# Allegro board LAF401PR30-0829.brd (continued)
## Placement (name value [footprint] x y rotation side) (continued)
CZ84  68P_0402_50V8J  [C_0402]  214.81 11.96 0 top
CZ85  100P_0402_50V8J  [C_0402]  214.84 14.93 0 top
CZ86  100P_0402_50V8J  [C_0402]  214.84 15.84 0 top
CZ87  100P_0402_50V8J  [C_0402]  214.84 16.76 0 top
CZ88  68P_0402_50V8J  [C_0402]  217.11 20.12 0 top
CZ89  68P_0402_50V8J  [C_0402]  217.11 21.14 0 top
CZ90  0.1U_0201_10V6K  [C_0201]  214.91 18.45 270 top
CZ91  100P_0402_50V8J  [C_0402]  215.27 13.99 0 top
CZ92  100P_0402_50V8J  [C_0402]  215.27 13.1 0 top
CZ93  0.1U_0201_10V6K  [C_0201]  279.91 45.97 270 top
CZ101  0.1U_0201_10V6K  [C_0201]  124.34 84.22 180 bottom
CZ103  0.1U_0201_10V6K  [C_0201]  123.44 29.37 90 top
CZ104  0.1U_0402_10V7K  [C_0402]  128.96 26.37 0 top
CZ106  0.1U_0201_10V6K  [C_0201]  144.56 86.63 0 bottom
CZ109  470P_0402_50V7K  [C_0402]  278.72 49.92 0 bottom
CZ110  470P_0402_50V7K  [C_0402]  278.72 50.81 0 bottom
CZ111  0.1U_0201_10V6K  [C_0201]  276.61 52.22 180 bottom
CZ112  0.1U_0201_10V6K  [C_0201]  204.43 9.68 180 top
CZ113  470P_0402_50V7K  [C_0402]  207.4 6.76 45 top
CZ114  1000P_0402_50V7K  [C_0402]  205.06 6.06 90 top
CZ115  0.1U_0201_10V6K  [C_0201]  206.56 3.05 270 top
CZ116  0.1U_0201_10V6K  [C_0201]  194.91 17.8 0 top
CZ117  470P_0402_50V7K  [C_0402]  194.94 17.04 0 top
CZ118  470P_0402_50V7K  [C_0402]  194.94 16.02 0 top
CZ119  0.1U_0201_10V6K  [C_0201]  277.41 46.63 180 bottom
CZ120  0.1U_0201_10V6K  [C_0201]  272.55 49.42 90 top
CZ121  470P_0402_50V7K  [C_0402]  270.52 48.23 270 top
CZ122  0.1U_0201_10V6K  [C_0201]  192.96 14.5 180 top
CZ124  2200P_0402_50V7K  [C_0402]  277.32 47.39 180 bottom
CZ125  0.1U_0201_10V6K  [C_0201]  277.25 73.39 90 top
CZ126  220P_0402_50V7K  [C_0402]  275.72 71.09 270 top
CZ127  1000P_0402_50V7K  [C_0402]  274.71 71.09 270 top
CZ128  0.1U_0201_10V6K  [C_0201]  272.93 73.55 90 top
CZ129  0.1U_0201_10V6K  [C_0201]  279.95 39.96 180 bottom
CZ130  470P_0402_50V7K  [C_0402]  281.31 41.5 270 bottom
CZ133  0.1U_0201_10V6K  [C_0201]  289.18 62.63 90 bottom
CZ134  0.01UF_0402_25V7K  [C_0402]  283.8 66.95 180 top
CZ135  0.22U_0402_10V6K  [C_0402]  282.88 65.99 0 top
CZ136  0.22U_0402_10V6K  [C_0402]  282.88 65.04 0 top
CZ141  0.22U_0402_10V6K  [C_0402]  282.88 63.14 0 top
CZ142  0.22U_0402_10V6K  [C_0402]  282.88 64.09 0 top
CZ197  470P_0402_50V7K  [C_0402]  270.69 53.36 0 top
CZ198  100P_0402_50V8J  [C_0402]  291.34 50.51 270 top
CZ200  0.1U_0402_25V6K  [C_0402]  114.66 86.02 180 bottom
CZ210  100P_0402_50V8J  [C_0402]  206.02 7.77 0 top
CZ211  100P_0402_50V8J  [C_0402]  205.72 3.27 270 top
CZ212  27P_0402_50V8J  [C_0402]  283.52 46.75 270 bottom
CZ1000  1U_0201_6.3V6M  [C_0201]  137.79 86.68 180 bottom
CZ1001  1U_0201_6.3V6M  [C_0201]  137.79 86.1 180 bottom
CZ1002  1U_0201_6.3V6M  [C_0201]  126.81 26.64 0 top
CZ1003  1U_0201_6.3V6M  [C_0201]  126.81 25.98 0 top
CZ1004  1U_0201_6.3V6M  [C_0201]  133.33 82.82 90 bottom
CZ1005  1U_0201_6.3V6M  [C_0201]  133.91 82.82 90 bottom
DA1  AZ5123-02S.R7G_SOT23-3  [L03ESDL5V0CC3-2_SOT23-3]  311.82 35.07 90 top
DA2  PESD5V0U2BT_SOT23-3  [L03ESDL5V0CC3-2_SOT23-3]  311.82 31.01 90 top
DA3  AZ5123-02S.R7G_SOT23-3  [L03ESDL5V0CC3-2_SOT23-3]  309.73 39.13 270 top
DA6  PESD5V0U2BT_SOT23-3  [L03ESDL5V0CC3-2_SOT23-3]  284.08 29.74 270 top
DA7  PESD5V0U2BT_SOT23-3  [L03ESDL5V0CC3-2_SOT23-3]  284.08 34.31 270 top
DA8  RB751S40_SOD523-2  [RB520SM-30T2R_EMD2-2]  293.81 42.02 0 top
DC1  RB751S40_SOD523-2  [RB520SM-30T2R_EMD2-2]  185.07 34.75 180 top
DC2  RB751S40_SOD523-2  [RB520SM-30T2R_EMD2-2]  183.37 36.02 0 top
DE1  BZV55-B5V6_SOD80C2  [BZV55-B5V1_SOD80C2]  266.88 40.68 180 top
DE2  RB751S40_SOD523-2  [RB520SM-30T2R_EMD2-2]  317.76 60.83 90 top
DI1  -  [L05ESDL5V0NA-4_SLP2510P8-10-9]  19.94 70.38 270 top
DI2  -  [AZC199-02SPR7G_SOT23-3]  24.14 71.27 270 top
DI3  -  [AZC199-02SPR7G_SOT23-3]  80.46 101.72 180 bottom
DI4  -  [L05ESDL5V0NA-4_SLP2510P8-10-9]  308.81 54.87 90 top
DI5  -  [AZC199-02SPR7G_SOT23-3]  309.12 50.82 180 top
DI6  -  [L05ESDL5V0NA-4_SLP2510P8-10-9]  80.41 102.2 180 top
DT1  -  [1N4148WS-7-F_SOD323-2]  38.67 98.57 180 bottom
DT2  -  [1N4148WS-7-F_SOD323-2]  38.67 96.79 180 bottom
DT3  -  [1N4148WS-7-F_SOD323-2]  35.69 94.45 270 bottom
DT4  -  [L30ESD24VC3-2_SOT23-3]  12.83 90.21 0 bottom
DT5  AZ5B75-01B_CSP0603P2Y  [ESD8011MUT5G_X3DFN2-2-S]  11.86 94.2 270 bottom
DT6  AZ5B75-01B_CSP0603P2Y  [ESD8011MUT5G_X3DFN2-2-S]  11.86 95.04 90 bottom
DT9  AZ5B75-01B_CSP0603P2Y  [ESD8011MUT5G_X3DFN2-2-S]  11.83 100.05 270 bottom
DT10  AZ5B75-01B_CSP0603P2Y  [ESD8011MUT5G_X3DFN2-2-S]  11.83 100.9 90 bottom
DT13  AZ5B75-01B_CSP0603P2Y  [ESD8011MUT5G_X3DFN2-2-S]  11.4 91.42 270 bottom
DT14  AZ5B75-01B_CSP0603P2Y  [ESD8011MUT5G_X3DFN2-2-S]  11.4 92.26 90 bottom
DT17  AZ5B75-01B_CSP0603P2Y  [ESD8011MUT5G_X3DFN2-2-S]  11.83 100.9 90 top
DT18  AZ5B75-01B_CSP0603P2Y  [ESD8011MUT5G_X3DFN2-2-S]  11.83 100.05 270 top
DT39  -  [L05ESDL5V0NA-4_SLP2510P8-10-9]  12.33 96.55 270 bottom
DT40  -  [L05ESDL5V0NA-4_SLP2510P8-10-9]  12.63 91.22 270 top
DV1  -  [BAT54CW_SOT323-3]  105.67 86.12 180 bottom
DV2  -  [BAT54CW_SOT323-3]  103.13 85.87 180 bottom
DV3  -  [BAT54CW_SOT323-3]  92.97 83.78 0 bottom
DV4  -  [AZC199-02SPR7G_SOT23-3]  116.44 87.33 90 bottom
DV5  -  [PJDLC05C_SOT23-3]  314.3 85.04 90 bottom
DV6  -  [PJDLC05C_SOT23-3]  314.3 80.98 90 bottom
DZ1  RB751S40_SOD523-2  [RB520SM-30T2R_EMD2-2]  216.57 9.38 180 top
DZ2  RB751S40_SOD523-2  [RB520SM-30T2R_EMD2-2]  216.57 10.65 180 top
DZ5  RB751S40_SOD523-2  [RB520SM-30T2R_EMD2-2]  292.83 49.17 90 top
DZ6  RB751S40_SOD523-2  [RB520SM-30T2R_EMD2-2]  293.53 45.75 90 top
DZ7  RB751S40_SOD523-2  [RB520SM-30T2R_EMD2-2]  221.31 22.52 180 top
DZ8  RB751S40_SOD523-2  [RB520SM-30T2R_EMD2-2]  154.44 38 90 top
DZ9  -  [BAT54CW_SOT323-3]  184 13.52 180 top
FD1  FIDUCIAL MARK~D  [FIDUCIAL_C40M80]  315.36 95.48 0 top
FD2  FIDUCIAL MARK~D  [FIDUCIAL_C40M80]  15.37 3.83 0 top
FD3  FIDUCIAL MARK~D  [FIDUCIAL_C40M80]  15.37 3.83 180 bottom
FD4  FIDUCIAL MARK~D  [FIDUCIAL_C40M80]  323.22 97.3 180 bottom
H1  -  [H_3P8]  87.65 73.4 0 top
H2  -  [H_3P8]  87.65 45.4 0 top
H3  -  [H_3P8]  144.25 81.75 0 top
H4  -  [H_3P8]  149.15 47.45 0 top
H5  -  [H_1P1N]  98.5 71.86 0 top
H6  -  [H_1P1N]  139.62 48.75 0 top
H7  -  [H_3P2]  234.9 15.5 0 top
H8  -  [H_3P2]  296.05 87.5 0 top
H9  H_2P3  [H_2P3-G]  141.95 118.9 0 top
H10  H_3P0  [H_3P0-G]  310.15 98.9 0 top
H12  H_2P5  [H_2P5-G]  323.65 22.4 0 top
H14  H_4P0  [H_4P0-G]  267.65 58.9 0 top
H15  H_4P0  [H_4P0-G]  269.65 101.4 0 top
H16  H_2P3  [H_2P3-G]  67.35 116.9 0 top
H17  H_4P0  [H_4P0-G]  113.15 2.1 0 top
H18  H_2P5  [H_2P5-G]  4.45 3 0 top
H20  H_4P0  [H_4P0-G]  202.75 37.1 0 top
H22  H_4P0  [H_4P0-G]  241 1.5 0 top
H23  H_2P5  [H_2P5-G]  6.25 106.1 0 top
H24  H_2P5  [H_2P5-G]  6.25 88 0 top
H25  H_2P2  [H_2P2-G]  4.45 8.4 0 top
H26  H_2P3  [H_2P3-G]  116.55 116.9 0 top
H28  H_2P5  [H_2P5-G]  268.15 106.3 0 top
H29  H_2P5  [H_2P5-G]  282.15 110.4 0 top
H32  H_2P6X3P6  [H_2P6X3P6-G]  318.05 22.4 90 top
H34  -  [H_3P3]  89.35 94.4 0 top
H35  -  [H_3P3]  123.75 94.4 0 top
H38  -  [H_3P8]  147.55 117.4 0 top
H42  -  [H_0P7N]  121.59 116.25 0 top
H43  -  [H_0P9N]  130.79 103.2 0 top
JAPS1  ACES_50506-01841-P01  [ACES_50506-01841-P01_18P]  317.63 62.25 90 bottom
JCRT1  CCM_C070546HR015M29CZR  [CCM_C070546HR015M29CZR_15P-T]  322.15 83.18 90 bottom
JDB1  JXT_FP241AH-006GAAM  [JXT_FP241AH-006GAAM_6P]  32.37 97.09 180 top
JDEG1  JXT_FP241AH-010GAAM  [JXT_FP241AH-010GAAM_10P]  275.98 77.9 270 bottom
JDIMM1  LCN_DAN05-Q0406-0103  [LCN_DAN05-Q0406-0103_260P]  39.28 13 180 bottom
JDIMM2  LCN_DAN05-Q0406-0103  [LCN_DAN05-Q0406-0103_260P]  120.28 13 180 bottom
JEDP1  ACES_50398-04041-001  [ACES_50398-04041-001_40P]  116.3 92.14 180 bottom
JESPI  JXT_FP241AH-010GAAM  [JXT_FP241AH-010GAAM_10P]  269.76 70.34 270 bottom
JFAN1  ACES_50271-0040N-001  [ACES_50271-0040N-001_4P]  267.69 44.49 50 bottom
JHDMI1  CONCR_099BKAC19YBLCNF  [CONCR_099BKAC19YBLCNF_19P]  98.55 111.32 0 bottom
JHP1  SINGA_2SJ3095-136111F  [SINGA_2SJ3095-136111F_7P-T]  316.45 38.4 90 bottom
JIR1  ACES_50208-0060N-P01  [ACES_50208-0060N-P01_6P]  76.83 92.5 90 bottom
JKBTP1  CVILU_CF5020FD0RK-05-NH  [CVILU_CF5020FD0RK-05-NH_20P-T]  213.13 22.65 270 top
JLED1  CVILU_CF5006FD0R0-05-NH  [CVILU_CF5006FD0R0-05-NH_6P]  284.4 51.15 0 top
JLOM1  SANTA_130456-831  [SANTA_130456-831_13P-T]  292.98 107.18 0 bottom
JNGFF1  CONCR_213AAAA42FA  [CONCR_213AAAA42FA_75P]  201.27 24.75 270 bottom
JNGFF2  CONCR_213BAAA42FA  [CONCR_213BAAA42FA_75P]  286.8 41.87 0 bottom
JNGFF3  LCN_DAN05-67356-0103  [LCN_DAN05-67356-0103_75P]  307.95 33.92 180 bottom
JRTC1  ACES_50271-0020N-001  [ACES_50271-0020N-001_2P]  61.25 78.28 90 bottom
JSATA1  ACES_59003-02006-002  [ACES_59003-02006-002_20P]  271.9 34.63 0 bottom
JSD1  T-SOL_156-2000302608_NR  [T-SOL_156-2000302608_19P_NR]  32.38 40.5 90 bottom
JSIM1  T-SOL_5-991503004000-6  [T-SOL_5-991503004000-6_8P-T]  123.74 105.88 0 bottom
JSPI1  ACES_50506-02041-P01  [ACES_50506-02041-P01_20P]  167.35 46.93 180 bottom
JSPK1  ACES_50278-00401-001  [ACES_50278-00401-001_4P]  264.99 29.6 90 top
JTAG1  @SHORT PADS~D  [SHORTPADS]  299.73 87.62 90 top
JUSB1  C-K_26230A-8K1A-02  [C-K_26230A-8K1A-02_9P-T]  313.1 46.35 270 bottom
JUSB2  LOTES_AUSB0014-P003A  [LOTES_AUSB0014-P003A_9P]  15.66 77.9 90 bottom
JUSB3  C-K_26210B-8K1A-02  [C-K_26210B-8K1A-02_9P]  84.05 107.02 0 bottom
JUSBC1  JAE_DX07BD24JJ2  [JAE_DX07BD24JJ2_24P-T]  7.55 94.43 90 bottom
JUSH1  CVILU_CF5026FD0RK-05-NH  [CVILU_CF5026FD0RK-05-NH_26P-T]  222.97 7.15 90 top
JXDP1  SAMTE_BSH-030-01-L-D-A  [SAMTE_BSH-030-01-L-D-A_60P]  75.45 35.84 180 top
LA5  BLM15PX600SN1D_2P  [MURAT_BLM15PX600SN1D_2P]  307.54 28.57 270 top
LA6  BLM15PD800SN1D_2P  [MURAT_BLM15PD800SN1D_2P]  288.85 30.18 180 top
LA7  BLM15PD800SN1D_2P  [MURAT_BLM15PD800SN1D_2P]  288.85 31.32 180 top
LA8  BLM15PD800SN1D_2P  [MURAT_BLM15PD800SN1D_2P]  288.87 36.76 270 top
LA9  BLM15PD800SN1D_2P  [MURAT_BLM15PD800SN1D_2P]  286.89 36.85 180 top
LA10  BLM15PX330SN1D_2P  [MURAT_BLM15PX330SN1D_2P]  309.38 39.13 0 bottom
LA11  BLM15PX330SN1D_2P  [MURAT_BLM15PX330SN1D_2P]  309.4 36.17 0 bottom
LA12  BLM15PX600SN1D_2P  [MURAT_BLM15PX600SN1D_2P]  294.5 32.78 180 top
LA13  HCB2012KF-121T50_2P  [TAI-T_HCB2012KF-121T50_2P]  300.21 43.97 90 top
LA14  BLM15PX600SN1D_2P  [MURAT_BLM15PX600SN1D_2P]  293.46 40.95 0 top
LA15  BLM15PX330SN1D_2P  [MURAT_BLM15PX330SN1D_2P]  308.13 37.67 0 top
LA16  BLM15PX330SN1D_2P  [MURAT_BLM15PX330SN1D_2P]  307.99 36.54 270 top
LC1  BLM15GA750SN1D_2P  [MURAT_BLM15GA750SN1D_2P]  126.5 33.4 270 top
LC2  BLM15GA750SN1D_2P  [MURAT_BLM15GA750SN1D_2P]  145.47 62.06 270 top
LE1  BLM15GA750SN1D_2P  [MURAT_BLM15GA750SN1D_2P]  220.48 21.38 0 top
LED3  LTW-C193DC-C_WHITE  [LED_LTW-C193DC-C_2P]  320.9 98.51 180 top
LGA1  -  [LNG2DMTR_LGA12_2X2]  273.72 45.23 270 bottom
LI3  EXC24CQ900U_4P  [PANAS_EXC24CQ900U_4P]  29.72 69.87 270 top
LI4  EXC24CQ900U_4P  [PANAS_EXC24CQ900U_4P]  77.35 100.09 270 bottom
LI7  EXC24CQ900U_4P  [PANAS_EXC24CQ900U_4P]  308.44 45.68 180 top
LI8  MCM1012B900F06BP_4P  [INPAQ_MCM1012B900F06BP_4P]  290.2 45.6 270 top
LI9  MCM1012B900F06BP_4P  [INPAQ_MCM1012B900F06BP_4P]  196.55 23.64 0 bottom
LI16  HCM1012GH900BP_4P  [INPAQ_HCM1012GH900BP_4P]  292.23 45.6 270 top
LI17  HCM1012GH900BP_4P  [INPAQ_HCM1012GH900BP_4P]  295.4 47.57 270 top
LL1  4.7UH_BRC2012T4R7MD_20%  [TAIYO_BRC2012T4R7MD_2P]  283.56 86.38 0 top
LT11  BLM15PX600SN1D_2P  [MURAT_BLM15PX600SN1D_2P]  18.62 88.87 90 top
LV1  BLM15PX221SN1D_2P  [MURAT_BLM15PX221SN1D_2P]  106.94 88.9 270 bottom
LV3  HCM1012GH900BP_4P  [TAIYO_MCF12102G900-T_4P-NPM]  98.41 104.23 90 top
LV6  HCM1012GH900BP_4P  [TAIYO_MCF12102G900-T_4P-NPM]  101.96 104.23 90 top
LV9  HCM1012GH900BP_4P  [TAIYO_MCF12102G900-T_4P-NPM]  108.31 104.23 90 top
LV12  HCM1012GH900BP_4P  [TAIYO_MCF12102G900-T_4P-NPM]  105.52 104.23 90 top
LV14  BLM15PX600SN1D_2P  [MURAT_BLM15PX600SN1D_2P]  275.6 55.39 90 bottom
LV16  BLM15BB470SN1D_2P  [MURAT_BLM15BB470SN1D_2P]  317.38 89.48 270 bottom
LV17  BLM15BB470SN1D_2P  [MURAT_BLM15BB470SN1D_2P]  316.11 89.48 270 bottom
LV18  BLM15BB470SN1D_2P  [MURAT_BLM15BB470SN1D_2P]  313.44 76.26 90 bottom
LV27  EXC24CQ900U_4P  [PANAS_EXC24CQ900U_4P]  120.66 86.27 270 bottom
LV30  BLM15PX600SN1D_2P  [MURAT_BLM15PX600SN1D_2P]  282.62 55.26 180 top
LZ1  EXC24CQ900U_4P  [PANAS_EXC24CQ900U_4P]  110.88 87.52 0 bottom
LZ2  BLM15GA750SN1D_2P  [MURAT_BLM15GA750SN1D_2P]  219.64 7.16 0 top
NOREF  -  []  268.15 106.3 0 top
NOREF#2  -  []  65.41 -32.24 0 top
NOREF#3  -  []  116.55 116.9 0 top
NOREF#4  -  []  72.27 161.56 0 top
NOREF#5  -  []  4.45 8.4 0 top
NOREF#6  -  []  296.05 87.5 0 top
NOREF#7  -  []  234.9 15.5 0 top
NOREF#8  -  []  269.65 101.4 0 top
NOREF#9  -  []  241 1.5 0 top
NOREF#10  -  []  282.15 110.4 0 top
NOREF#11  -  []  186.38 29.29 0 top
NOREF#12  -  []  89.63 31.42 0 top
NOREF#13  -  []  317.55 22.4 0 top
NOREF#14  -  []  4.45 3 0 top
NOREF#15  -  []  168.09 76.17 0 top
NOREF#16  -  []  6.25 88 0 top
NOREF#17  -  []  310.15 98.9 0 top
NOREF#18  -  []  149.15 47.45 0 top
NOREF#19  -  []  87.65 45.4 0 top
NOREF#20  -  []  87.65 73.4 0 top
NOREF#21  -  []  113.15 2.1 0 top
NOREF#22  -  []  145.04 20.91 0 top
NOREF#23  -  []  41.75 18.36 0 top
NOREF#24  -  []  67.35 116.9 0 top
NOREF#25  -  []  87.44 26.31 0 top
NOREF#26  -  []  147.55 117.4 0 top
NOREF#27  -  []  202.75 37.1 0 top
NOREF#28  -  []  323.65 22.4 0 top
NOREF#29  -  []  267.65 58.9 0 top
NOREF#30  -  []  108.27 26.24 90 top
NOREF#31  -  []  141.95 118.9 0 top
NOREF#32  -  []  6.25 106.1 0 top
NOREF#33  -  []  144.25 81.75 0 top
NOREF#34  -  []  171.96 86.63 180 bottom
NOREF#35  -  []  127.64 31.64 180 bottom
NOREF#36  -  []  81.58 28.4 180 bottom
PBATT1  DEREN_40-42251-01001RHF  [DEREN_40-42251-01001RHF_10P-T]  26 12.35 180 bottom
PC1  2200P_0402_50V7K  [C_0402]  22.53 7.1 270 top
PC2  2200P_0402_50V7K  [C_0402]  61.19 78.43 0 top
PC3  1U_0603_25V6K  [C_0603]  57.54 77.49 90 top
PC4  0.022U_0603_50V7K  [C_0603]  46.77 80.85 0 top
PC5  1000P_0603_50V7K  [C_0603]  54.62 87.74 180 bottom
PC6  0.022U_0603_50V7K  [C_0603]  48.71 90.76 0 top
PC7  0.1U_0603_25V7K  [C_0603]  53.78 89.06 270 top
PC8  10U_0805_25V6K  [C_0805]  52.3 86.08 0 top
PC9  0.1U_0402_10V7K  [C_0402]  61.84 96.75 90 bottom
PC10  2.2U_0402_10V6M  [C_0402]  73.78 104.73 0 top
PC11  1000P_0603_50V7K  [C_0603]  72.08 101.17 90 top
PC100  0.1U 25V K X5R 0402  [C_0402]  157.25 117.58 180 bottom
PC102  0.1U_0603_25V7K  [C_0603]  159.77 110.25 180 top
PC103  100P_0402_50V8J  [C_0402]  157.26 117.59 180 top
PC104  10U_0805_25V6K  [C_0805]  157.19 115.59 180 bottom
PC105  10U_0805_25V6K  [C_0805]  157.19 115.59 180 top
PC106  22UF_0805_6.3V6M  [C_0805]  149.36 106.44 90 bottom
PC107  22UF_0805_6.3V6M  [C_0805]  151.14 104.26 90 bottom
PC108  22UF_0805_6.3V6M  [C_0805]  152.85 104.26 90 top
PC109  22UF_0805_6.3V6M  [C_0805]  149.36 106.44 90 top
PC110  22UF_0805_6.3V6M  [C_0805]  152.85 104.26 90 bottom
PC111  4.7U_0603_6.3V6K  [C_0603]  154.27 109.06 180 top
PC112  680P_0603_50V7K  [C_0603]  160.57 108.73 270 bottom
PC113  1000P_0402_50V7K  [C_0402]  152.45 112.46 180 top
PC114  0.1U_0603_25V7K  [C_0603]  162.33 112 0 bottom
PC115  0.1U 25V K X5R 0402  [C_0402]  163.39 117.54 90 bottom
PC116  100P_0402_50V8J  [C_0402]  163.39 117.54 90 top
PC117  10U_0805_25V6K  [C_0805]  164.44 118.06 0 bottom
PC118  10U_0805_25V6K  [C_0805]  164.44 118.06 0 top
PC119  4.7U_0603_6.3V6K  [C_0603]  171.2 111.46 0 bottom
PC120  22UF_0805_6.3V6M  [C_0805]  170.95 101.06 0 top
PC121  22UF_0805_6.3V6M  [C_0805]  170.92 102.84 0 top
PC122  22UF_0805_6.3V6M  [C_0805]  170.95 104.59 0 top
PC123  22UF_0805_6.3V6M  [C_0805]  171.24 101.05 0 bottom
PC124  22UF_0805_6.3V6M  [C_0805]  171.24 102.82 0 bottom
PC125  680P_0603_50V7K  [C_0603]  162.5 106.76 270 bottom
PC126  4.7U_0603_6.3V6K  [C_0603]  171.2 112.67 0 bottom
PC127  1000P_0402_50V7K  [C_0402]  171.19 114.64 0 bottom
PC128  4.7U_0603_6.3V6K~D  [C_0603]  171.39 115.59 90 bottom
PC129  22UF_0805_6.3V6M  [C_0805]  151.14 104.26 90 top
PC130  22UF_0805_6.3V6M  [C_0805]  171.24 104.6 0 bottom
PC131  100P_0402_50V8J  [C_0402]  164.65 116.73 0 top
PC132  100P_0402_50V8J  [C_0402]  171.19 113.75 0 bottom
PC133  1U_0402_25V6K  [C_0402]  161.73 113.18 0 top
PC134  100P_0402_50V8J  [C_0402]  161.73 114.06 0 top
PC135  100P_0402_50V8J  [C_0402]  161.73 115.84 0 top
PC136  1U_0402_25V6K  [C_0402]  161.73 114.95 0 top
PC137  100P_0402_50V8J  [C_0402]  159.96 114.08 270 bottom
PC138  1U_0402_25V6K  [C_0402]  160.77 119.08 0 bottom
PC139  27P_0402_50V8J  [C_0402]  159.91 119.08 180 bottom
PC140  1U_0402_25V6K  [C_0402]  160.85 114.08 270 bottom
PC141  100P_0402_50V8J  [C_0402]  154.26 104.74 90 top
PC142  100P_0402_50V8J  [C_0402]  154.03 107.97 180 top
PC143  100P_0402_50V8J  [C_0402]  157.67 118.52 180 top
PC144  100P_0402_50V8J  [C_0402]  171.56 99.71 0 bottom
PC145  100P_0402_50V8J  [C_0402]  148.01 106.93 90 top
PC200  10U_0805_25V6K  [C_0805]  42.93 47.62 90 bottom
PC201  10U_0805_25V6K  [C_0805]  42.93 47.62 90 top
PC202  18P_0402_50V8J  [C_0402]  41.34 47.88 90 bottom
PC203  100P_0402_50V8J  [C_0402]  41.34 47.88 90 top
PC204  680P_0603_50V7K  [C_0603]  48.15 48.98 180 top
PC205  0.1U_0603_16V7K  [C_0603]  50.26 47.44 0 top
PC206  1U_0402_6.3V6K  [C_0402]  48.19 45.63 270 bottom
PC207  2.2U_0402_6.3V6M  [C_0402]  47.3 45.64 270 bottom
PC208  330P_0402_50V7K  [C_0402]  45.28 44.65 90 bottom
PC209  22U_0603_6.3V6M  [C_0603]  48.39 51.23 90 bottom
PC210  22U_0603_6.3V6M  [C_0603]  56.84 41.93 0 top
PC211  22U_0603_6.3V6M  [C_0603]  56.84 44.47 0 top
PC212  22U_0603_6.3V6M  [C_0603]  56.84 43.2 0 top
PC213  22U_0603_6.3V6M  [C_0603]  56.84 43.2 0 bottom
PC214  10U_0603_6.3V6M  [C_0603]  56.84 41.93 0 bottom
PC216  2200P_0402_50V7K  [C_0402]  48.65 41.85 90 bottom
PC217  100P_0402_50V8J  [C_0402]  46.19 43.79 180 bottom
PC218  1U_0402_10V6K  [C_0402]  45.61 51.14 90 bottom
PC219  22U_0603_6.3V6M  [C_0603]  47.15 51.23 90 bottom
PC221  0.1U_0402_10V7K  [C_0402]  42.04 51.19 90 bottom
PC222  0.1U_0402_10V7K  [C_0402]  43.85 51.15 90 bottom
PC223  10U_0603_6.3V6M  [C_0603]  56.84 44.47 0 bottom
PC224  27P_0402_50V8J  [C_0402]  45.73 51.07 90 top
PC301  0.1U_0402_25V6  [C_0402]  179.13 97.43 0 top
PC302  680P_0603_50V7K  [C_0603]  174.57 91.78 90 bottom
PC303  100P_0402_50V7K  [C_0402]  179.13 97.43 0 bottom
PC304  0.1U_0603_25V7K  [C_0603]  177.87 93.17 180 bottom
PC305  10U_0603_25V6M  [C_0603]  179.2 98.51 0 top
PC306  10U_0603_25V6M  [C_0603]  179.2 98.51 0 bottom
PC307  330P_0402_50V7K  [C_0402]  185.93 93.1 90 bottom
PC308  22U_0603_6.3V6M  [C_0603]  183.39 81.55 0 bottom
PC309  22U_0603_6.3V6M  [C_0603]  183.39 82.82 0 top
PC310  22U_0603_6.3V6M  [C_0603]  183.39 82.82 0 bottom
PC311  22U_0603_6.3V6M  [C_0603]  183.39 81.55 0 top
PC312  4.7U_0603_6.3V6K  [C_0603]  184.28 91.9 0 bottom
PC313  4.7U_0603_6.3V6K  [C_0603]  184.28 90.7 0 bottom
PC314  100P_0402_50V7K  [C_0402]  183.65 80.49 0 bottom
PC315  27P_0402_50V8J  [C_0402]  183.65 79.55 0 bottom
PC316  1U_0402_25V6K  [C_0402]  183.65 78.63 0 bottom
PC317  100P_0402_50V7K  [C_0402]  179.2 100.48 0 bottom
PC318  1U_0402_25V6K  [C_0402]  179.2 99.59 0 bottom
PC319  100P_0402_50V7K  [C_0402]  176.97 99.87 90 top
PC320  100P_0402_50V7K  [C_0402]  177.96 99.87 90 top
PC321  1U_0402_25V6K  [C_0402]  175.98 99.87 90 top
PC401  680P_0402_50V7K  [C_0402]  137.41 107.73 0 top
PC402  0.1U_0402_25V6  [C_0402]  137.46 111.41 180 top
PC403  10U_0603_10V6M  [C_0603]  138.44 113.68 90 top
PC404  10U_0603_10V6M  [C_0603]  139.64 113.68 90 top
PC406  22U_0603_6.3V6M  [C_0603]  143.26 105.75 0 bottom
PC407  22U_0603_6.3V6M  [C_0603]  140.98 103.52 180 top
PC408  0.1U_0402_25V6  [C_0402]  141.69 113.37 90 top
PC409  100P_0402_50V7K  [C_0402]  140.77 113.36 90 top
PC410  470P_0402_50V7K  [C_0402]  144.71 111.42 0 top
PC411  0.1U_0402_25V6  [C_0402]  127.92 113.77 90 top
PC412  10U_0603_10V6M  [C_0603]  131.11 115.59 90 top
PC413  10U_0603_10V6M  [C_0603]  132.33 115.6 90 top
PC415  22U_0603_6.3V6M  [C_0603]  131.38 106.1 270 top
PC416  22U_0603_6.3V6M  [C_0603]  133.43 107.06 0 top
PC417  0.1U_0402_25V6  [C_0402]  130.03 116.43 180 top
PC418  2200P_0402_50V7K  [C_0402]  130.04 115.53 180 top
PC419  680P_0402_50V7K  [C_0402]  127 110.11 0 top
PC420  470P_0402_50V7K  [C_0402]  133.77 112.18 0 top
PC424  22U_0603_6.3V6M  [C_0603]  130.13 106.08 270 top
PC425  10U_0603_6.3V6M  [C_0603]  140.98 103.52 180 bottom
PC426  10U_0603_6.3V6M  [C_0603]  143.26 105.75 0 top
PC501  22U_0603_6.3V6M  [C_0603]  119.71 103.27 90 top
PC502  22U_0603_6.3V6M  [C_0603]  125.35 107.46 90 top
PC503  68P_0402_50V8J  [C_0402]  120.07 109.68 0 top
PC504  22U_0603_6.3V6M  [C_0603]  120.94 103.26 90 top
PC505  0.1U_0402_16V7K  [C_0402]  120.61 105.84 180 top
PC506  680P_0402_50V7K  [C_0402]  126.04 106.47 180 top
PC513  .1U_0402_16V7K  [C_0402]  197.61 3.11 270 top
PC514  4.7U_0603_6.3V6K  [C_0603]  196.56 6.33 180 top
PC515  0.01UF_0402_25V7K  [C_0402]  191.01 4.17 0 top
PC516  22U_0603_6.3V6M  [C_0603]  192.24 6.45 0 top
PC601  680P_0402_50V7K  [C_0402]  65.35 43.79 90 bottom
PC602  0.1U_0402_25V6  [C_0402]  72.04 50.72 180 bottom
PC603  1U_0603_10V6K  [C_0603]  74.37 47.96 0 top
PC604  0.22U_0603_25V7K  [C_0603]  72.65 47.92 0 bottom
PC605  47P_0402_50V8J~D  [C_0402]  74.43 52.61 270 top
PC606  100U_D_20VM_R55M  [C_D]  50.75 66.64 90 bottom
PC607  100U_D_20VM_R55M  [C_D]  46.03 66.64 90 bottom
PC608  10U 25V M X5R 0603 MURATA ZRB  [C_0603]  70.87 86.53 270 bottom
PC611  0.22U_0603_16V7K  [C_0603]  66.3 86.57 90 bottom
PC612  10U 25V M X5R 0603 MURATA ZRB  [C_0603]  70.87 86.53 270 top
PC613  330P_0402_50V7K  [C_0402]  70.03 52.37 90 bottom
PC614  2200P_0402_50V7K  [C_0402]  67.39 52.37 90 bottom
PC616  33P_0402_50V8J  [C_0402]  68.25 52.32 0 bottom
PC617  1200P_0402_50V7K  [C_0402]  69.54 57.85 0 top
PC618  330P_0402_50V7K  [C_0402]  70.44 57.8 180 bottom
PC619  0.01UF_0402_25V7K  [C_0402]  70.44 55.2 180 bottom
PC620  0.082U_0402_16V7K  [C_0402]  68.64 56.04 270 top
PC621  680P_0402_50V7K  [C_0402]  71.3 56.14 270 top
PC622  680P_0603_50V7K  [C_0603]  73.03 86.57 270 top
PC624  0.033U_0402_16V7K  [C_0402]  65.99 55.18 90 bottom
PC625  330P_0402_50V7K  [C_0402]  66.5 50.91 180 bottom
PC626  0.047U_0402_25V7K  [C_0402]  66.88 55.18 90 bottom
PC627  2200P_0402_50V7K  [C_0402]  65.98 56.1 270 top
PC628  33P 50V J NPO 0402  [C_0402]  69.89 47.07 90 bottom
PC629  2200P_0402_50V7K  [C_0402]  65.02 46.35 180 bottom
PC630  2200P_0402_50V7K  [C_0402]  62.79 46.12 180 top
PC631  4700P_0402_25V7K  [C_0402]  71.75 48.09 180 bottom
PC632  1000P_0402_50V7K  [C_0402]  71.77 44.79 0 top
PC633  4700P 50V K X7R 0402  [C_0402]  71.81 42.13 90 top
PC635  0.022U_0402_16V7K  [C_0402]  65.09 56.96 90 top
PC636  33P_0402_50V8J  [C_0402]  65.01 47.21 90 bottom
PC637  0.033U 25V K X7R 0402  [C_0402]  73.53 42.13 90 top
PC638  0.022U_0402_16V7K  [C_0402]  64.2 56.96 90 top
PC639  1500P_0402_50V7K  [C_0402]  61.87 52.6 180 top
PC640  2200P_0402_50V7K  [C_0402]  67.95 42.91 90 bottom
PC641  .1U_0402_16V7K  [C_0402]  66.86 56.98 0 bottom
PC642  0.033U_0402_16V7K  [C_0402]  62.79 48.76 270 top
PC643  330P_0402_50V7K  [C_0402]  68.97 47.05 90 bottom
PC644  .1U_0402_16V7K  [C_0402]  74.44 43.87 90 top
PC645  .1U_0402_16V7K  [C_0402]  60.13 47 270 top
PC646  0.047U_0402_25V7K  [C_0402]  61.9 48.76 270 top
PC647  680P_0402_50V7K  [C_0402]  60.95 54.5 0 top
PC649  0.01UF_0402_25V7K  [C_0402]  69.73 43.83 270 bottom
PC650  0.082U_0402_16V7K  [C_0402]  68.82 44.71 0 bottom
PC651  330P_0402_50V7K  [C_0402]  60.95 51.33 0 top
PC652  330P_0402_50V7K  [C_0402]  68.84 43.83 270 bottom
PC653  0.082U_0402_16V7K  [C_0402]  62.74 50.96 270 top
PC654  0.01UF_0402_25V7K  [C_0402]  60.95 50.06 0 top
PC655  0.22U_0603_16V7K  [C_0603]  53.59 72.26 0 bottom
PC656  10U 25V M X5R 0603 MURATA ZRB  [C_0603]  53.59 68.62 0 bottom
PC657  10U 25V M X5R 0603 MURATA ZRB  [C_0603]  53.59 69.82 0 bottom
PC658  10U 25V M X5R 0603 MURATA ZRB  [C_0603]  53.59 68.62 0 top
PC659  0.1U_0402_25V6K~D  [C_0402]  58.07 74.01 0 top
PC660  2200P_0402_50V7K  [C_0402]  58.07 74.92 0 top
PC661  1U_0402_10V6K  [C_0402]  58.78 68.37 0 top
PC662  680P_0603_50V7K  [C_0603]  63.11 68.85 180 top
PC663  0.22U_0603_16V7K  [C_0603]  54.37 62.93 0 bottom
PC664  10U 25V M X5R 0603 MURATA ZRB  [C_0603]  58.26 66.77 0 top
PC665  10U 25V M X5R 0603 MURATA ZRB  [C_0603]  58.26 66.74 0 bottom
PC668  1U_0402_10V6K  [C_0402]  58.63 57.3 0 bottom
PC669  1U_0402_10V6K  [C_0402]  55.58 59.71 90 bottom
PC670  680P_0603_50V7K  [C_0603]  63.11 67.61 180 top
PC671  0.22U_0603_16V7K  [C_0603]  63.06 78.86 0 top
PC672  10U 25V M X5R 0603 MURATA ZRB  [C_0603]  66.02 81.12 0 top
PC673  10U 25V M X5R 0603 MURATA ZRB  [C_0603]  66.02 82.36 0 top
PC674  10U 25V M X5R 0603 MURATA ZRB  [C_0603]  58.26 65.58 0 top
PC675  10U 25V M X5R 0603 MURATA ZRB  [C_0603]  58.26 65.55 0 bottom
PC676  1U_0402_10V6K  [C_0402]  55.91 69.82 90 bottom
PC677  1U_0402_10V6K  [C_0402]  63 76.95 90 bottom
PC678  680P_0603_50V7K  [C_0603]  69.54 77.23 90 top
PC682  10U 25V M X5R 0603 MURATA ZRB  [C_0603]  53.59 69.82 0 top
PC683  10U 25V M X5R 0603 MURATA ZRB  [C_0603]  66.02 81.12 0 bottom
PC684  10U 25V M X5R 0603 MURATA ZRB  [C_0603]  66.02 82.36 0 bottom
PC685  1U_0402_10V6K  [C_0402]  69.09 83.61 0 bottom
PC686  0.1U_0402_50V8J  [C_0402]  59.57 72.05 0 top
PC687  0.1U_0402_50V8J  [C_0402]  58.4 64.51 0 top
PC688  0.1U_0402_50V8J  [C_0402]  64.01 82.47 90 bottom
PC689  27P_0402_50V8J  [C_0402]  50.83 56.72 270 bottom
PC690  1U_0402_25V6K  [C_0402]  48.06 56.7 270 bottom
PC691  18P_0402_50V8J  [C_0402]  49.92 56.72 270 bottom
PC692  12P_0402_50V8J  [C_0402]  48.98 56.7 270 bottom
PC697  1U_0402_10V6K  [C_0402]  66.12 75.02 0 top
PC902  0.1U_0402_25V6  [C_0402]  5.91 20.66 180 top
PC903  100P_0402_50V8J  [C_0402]  5.91 20.66 180 bottom
PC904  10U_0805_25VAK  [C_0805]  6.05 23.7 180 bottom
PC905  10U_0805_25VAK  [C_0805]  6.05 21.99 180 top
PC906  10U_0805_25VAK  [C_0805]  6.05 21.99 180 bottom
PC909  15U_B2_25VM_R100M  [C_B2]  7.29 27.89 0 bottom
PC911  10U_0805_25VAK  [C_0805]  6.05 23.7 180 top
PC913  10U_0805_25VAK  [C_0805]  29.68 13.86 180 top
PC914  10U_0805_25VAK  [C_0805]  29.68 13.86 180 bottom
PC915  10U_0805_25VAK  [C_0805]  31.51 8.27 0 top
PC916  10U_0805_25VAK  [C_0805]  31.51 8.27 0 bottom
PC918  100P_0402_50V8J  [C_0402]  10.93 13.86 90 top
PC921  15U_B2_25VM_R100M  [C_B2]  25.79 15.89 270 bottom
PC925  4.7U_0402_6.3V6M  [C_0402]  16.41 22.5 0 top
PC926  1U 25V K X5R 0402  [C_0402]  16.41 21.53 270 top
PC927  1U 25V K X5R 0402  [C_0402]  17.33 21.48 0 top
PC928  100P_0402_50V8J  [C_0402]  35.39 19.89 180 top
PC929  1U_0402_25V6K  [C_0402]  35.39 20.85 180 top
PC930  0.22U_0603_25V7K  [C_0603]  20.83 23.32 270 top
PC931  1U_0603_25V6  [C_0603]  10.99 20.27 0 top
PC932  1U_0402_6.3V6K  [C_0402]  20.33 16.83 90 bottom
PC933  1U_0402_6.3V6K  [C_0402]  13.29 18.69 180 bottom
PC934  0.22U_0603_25V7K  [C_0603]  24.26 16.72 180 top
PC935  10U_0805_25VAK  [C_0805]  31.51 6.44 0 bottom
PC936  10U_0805_25VAK  [C_0805]  31.51 6.44 0 top
PC937  4700P_0402_25V7K  [C_0402]  28.15 7.16 270 top
PC938  10P_0402_50V8J  [C_0402]  13.55 12.44 180 top
PC939  0.1U_0402_25V6  [C_0402]  22.71 17.62 0 bottom
PC940  680P_0603_50V7K  [C_0603]  15.22 28.63 270 top
PC941  680P_0603_50V7K  [C_0603]  32.45 23.2 270 top
PC942  1U 25V K X5R 0402  [C_0402]  24.27 15.64 180 top
PC943  560P_0402_50V7K  [C_0402]  17.27 12.39 270 top
PC944  0.01UF_0402_25V7K  [C_0402]  16.37 10.63 0 top
PC945  1U_0402_25V6M  [C_0402]  22.46 13.45 90 top
PC946  0.22U_0402_25V6K  [C_0402]  24.34 12.21 180 top
PC947  0.1U_0402_25V6  [C_0402]  18.17 10.05 0 top
PC949  0.1U_0402_10V7K  [C_0402]  30.74 29.02 90 top
PC950  0.1U_0402_25V6  [C_0402]  20.99 11.49 90 top
PC951  10U_0805_25VAK  [C_0805]  6.05 25.42 180 top
PC952  10U_0805_25VAK  [C_0805]  6.05 25.42 180 bottom
PC955  0.1U_0402_25V6  [C_0402]  13.29 16.91 180 bottom
PC956  100P_0402_50V8J  [C_0402]  51.76 56.74 270 bottom
PC957  100P_0402_50V8J  [C_0402]  34.12 13.92 270 top
PC958  18P_0402_50V8J  [C_0402]  35.9 13.92 270 top
PC959  27P_0402_50V8J  [C_0402]  35.01 13.92 270 top
PC1001  22U_0603_6.3V6M  [C_0603]  82.81 79.46 90 top
PC1002  22U_0603_6.3V6M  [C_0603]  84.46 68.53 270 top
PC1003  22U_0603_6.3V6M  [C_0603]  113.67 62.18 270 top
PC1004  22U_0603_6.3V6M  [C_0603]  85.67 68.08 270 top
PC1005  22U_0603_6.3V6M  [C_0603]  118.56 58.63 0 top
PC1006  22U_0603_6.3V6M  [C_0603]  112.46 59.9 180 top
PC1007  22U_0603_6.3V6M  [C_0603]  118.56 62.31 0 top
PC1008  22U_0603_6.3V6M  [C_0603]  84.02 79.46 90 bottom
PC1009  22U_0603_6.3V6M  [C_0603]  81.6 79.46 90 bottom
PC1010  22U_0603_6.3V6M  [C_0603]  85.67 68.09 270 bottom
PC1011  22U_0603_6.3V6M  [C_0603]  81.6 79.46 90 top
PC1012  22U_0603_6.3V6M  [C_0603]  118.56 57.42 0 top
PC1013  22U_0603_6.3V6M  [C_0603]  83.25 68.79 270 bottom
PC1014  22U_0603_6.3V6M  [C_0603]  107.45 58.95 270 top
PC1015  22U_0603_6.3V6M  [C_0603]  103.83 61.42 270 top
PC1016  22U_0603_6.3V6M  [C_0603]  105.03 61.42 270 top
PC1017  22U_0603_6.3V6M  [C_0603]  83.25 57.93 270 top
PC1018  22U_0603_6.3V6M  [C_0603]  85.54 62.95 90 bottom
PC1019  22U_0603_6.3V6M  [C_0603]  105.03 63.84 270 top
PC1020  22U_0603_6.3V6M  [C_0603]  103.83 63.84 270 top
PC1021  22U_0603_6.3V6M  [C_0603]  107.45 61.42 270 top
PC1022  22U_0603_6.3V6M  [C_0603]  105.03 56.53 270 top
PC1023  22U_0603_6.3V6M  [C_0603]  102.48 64.75 180 top
PC1024  22U_0603_6.3V6M  [C_0603]  106.24 63.84 270 top
PC1025  22U_0603_6.3V6M  [C_0603]  84.27 62.95 90 top
PC1026  22U_0603_6.3V6M  [C_0603]  106.24 58.95 270 top
PC1030  1U_0201_6.3V6M  [C_0201]  117.01 67.11 90 top
PC1031  1U_0201_6.3V6M  [C_0201]  119.18 65.01 90 top
PC1032  1U_0201_6.3V6M  [C_0201]  117.63 67.14 0 top
PC1033  1U_0201_6.3V6M  [C_0201]  118.28 64.97 90 top
PC1034  1U_0201_6.3V6M  [C_0201]  113.71 65.63 180 top
PC1035  1U_0201_6.3V6M  [C_0201]  113.99 57 90 top
PC1036  1U_0201_6.3V6M  [C_0201]  114.66 64.93 90 top
PC1037  1U_0201_6.3V6M  [C_0201]  113.67 68.09 180 top
PC1038  1U_0201_6.3V6M  [C_0201]  116.51 64.98 90 top
PC1039  1U_0201_6.3V6M  [C_0201]  117.41 64.93 90 top
PC1040  1U_0201_6.3V6M  [C_0201]  104.63 64.95 90 top
PC1041  1U_0201_6.3V6M  [C_0201]  106.46 64.95 90 top
PC1042  1U_0201_6.3V6M  [C_0201]  103.71 64.95 90 top
PC1043  1U_0201_6.3V6M  [C_0201]  105.56 64.94 90 top
PC1044  1U_0201_6.3V6M  [C_0201]  102.31 63.18 90 top
PC1045  1U_0201_6.3V6M  [C_0201]  100.65 57.96 270 top
PC1046  1U_0201_6.3V6M  [C_0201]  102.58 65.7 180 top
PC1047  1U_0201_6.3V6M  [C_0201]  101.49 61.63 180 top
PC1048  1U_0201_6.3V6M  [C_0201]  102.88 60.42 180 top
PC1049  1U_0201_6.3V6M  [C_0201]  101.07 63.16 90 top
PC1050  1U_0201_6.3V6M  [C_0201]  113.71 65.07 180 top
PC1051  1U_0201_6.3V6M  [C_0201]  118.74 63.28 0 top
PC1052  1U_0201_6.3V6M  [C_0201]  118.73 63.85 0 top
PC1053  1U_0201_6.3V6M  [C_0201]  118.31 55.92 0 top
PC1055  1U_0201_6.3V6M  [C_0201]  102.38 61.05 180 top
PC1056  1U_0201_6.3V6M  [C_0201]  100.94 59.74 270 top
PC1057  22U_0603_6.3V6M  [C_0603]  85.1 87.65 90 top
PC1058  22U_0603_6.3V6M  [C_0603]  86.3 87.65 90 top
PC1059  22U_0603_6.3V6M  [C_0603]  122.32 63.54 180 top
PC1060  22U_0603_6.3V6M  [C_0603]  83.89 87.65 90 top
PC1061  22U_0603_6.3V6M  [C_0603]  82.81 79.46 90 bottom
PC1062  330U_D2_2.5VM_R9M  [C_D2]  75.29 73.17 270 bottom
PC1063  330U_D2_2.5VM_R9M  [C_D2]  75.29 63.1 270 bottom
PC1064  22U_0603_6.3V6M  [C_0603]  112.46 58.63 180 top
PC1065  22U_0603_6.3V6M  [C_0603]  112.46 61.17 180 top
PC1066  22U_0603_6.3V6M  [C_0603]  116.15 56.09 90 top
PC1067  22U_0603_6.3V6M  [C_0603]  86.87 67.52 270 top
PC1068  22U_0603_6.3V6M  [C_0603]  116.15 59.84 270 top
PC1069  22U_0603_6.3V6M  [C_0603]  114.94 62.18 270 top
PC1070  22U_0603_6.3V6M  [C_0603]  118.56 61.11 0 top
PC1071  22U_0603_6.3V6M  [C_0603]  118.56 59.84 0 top
PC1072  22U_0603_6.3V6M  [C_0603]  84.46 68.53 270 bottom
PC1073  22U_0603_6.3V6M  [C_0603]  117.42 56.09 90 top
PC1074  22U_0603_6.3V6M  [C_0603]  117.42 59.84 270 top
PC1075  22U_0603_6.3V6M  [C_0603]  84.02 79.46 90 top
PC1076  22U_0603_6.3V6M  [C_0603]  113.67 59.84 270 top
PC1077  22U_0603_6.3V6M  [C_0603]  114.94 56.09 90 top
PC1078  22U_0603_6.3V6M  [C_0603]  116.15 62.18 270 top
PC1079  22U_0603_6.3V6M  [C_0603]  117.42 62.18 270 top
PC1080  22U_0603_6.3V6M  [C_0603]  86.87 67.52 270 bottom
PC1081  22U_0603_6.3V6M  [C_0603]  83.25 68.79 270 top
PC1082  22U_0603_6.3V6M  [C_0603]  114.94 59.84 270 top
PC1083  1U_0201_6.3V6M  [C_0201]  115.03 63.34 0 top
PC1084  1U_0201_6.3V6M  [C_0201]  116.45 67.11 90 top
PC1085  1U_0201_6.3V6M  [C_0201]  117.63 67.71 0 top
PC1086  1U_0201_6.3V6M  [C_0201]  117.44 66.54 180 top
PC1087  1U_0201_6.3V6M  [C_0201]  118.81 66.53 90 top
PC1088  1U_0201_6.3V6M  [C_0201]  120.49 68.12 0 top
PC1089  1U_0201_6.3V6M  [C_0201]  115.42 64.78 90 top
PC1090  1U_0201_6.3V6M  [C_0201]  116.25 66.53 180 top
PC1091  1U_0201_6.3V6M  [C_0201]  115.09 53.6 0 top
PC1092  1U_0201_6.3V6M  [C_0201]  116.88 63.02 0 top
PC1093  1U_0201_6.3V6M  [C_0201]  116.88 63.59 0 top
PC1094  1U_0201_6.3V6M  [C_0201]  113.26 63.58 0 top
PC1095  1U_0201_6.3V6M  [C_0201]  118.32 56.5 0 top
PC1096  1U_0201_6.3V6M  [C_0201]  113.26 63.01 0 top
PC1097  1U_0201_6.3V6M  [C_0201]  115.89 67.11 90 top
PC1098  1U_0201_6.3V6M  [C_0201]  115.07 54.18 0 top
PC1099  1U_0201_6.3V6M  [C_0201]  116.86 53.61 180 top
PC1127  330U_D2_2.5VM_R9M  [C_D2]  80.02 73.17 270 bottom
PC1128  330U_D2_2.5VM_R9M  [C_D2]  80.02 63.1 270 bottom
PC1129  22U_0603_6.3V6M  [C_0603]  102.18 59.26 270 top
PC1132  22U_0603_6.3V6M  [C_0603]  106.24 61.42 270 top
PC1133  22U_0603_6.3V6M  [C_0603]  103.83 56.53 270 top
PC1134  22U_0603_6.3V6M  [C_0603]  105.03 58.95 270 top
PC1136  22U_0603_6.3V6M  [C_0603]  106.24 56.53 270 top
PC1137  22U_0603_6.3V6M  [C_0603]  103.83 58.95 270 top
PC1139  22U_0603_6.3V6M  [C_0603]  123.11 56.24 180 top
PC1140  22U_0603_6.3V6M  [C_0603]  124.07 56.26 0 top
PC1141  22U_0603_6.3V6M  [C_0603]  122.36 62.35 180 top
PC1142  22U_0603_6.3V6M  [C_0603]  122.45 59.95 180 top
PC1143  22U_0603_6.3V6M  [C_0603]  86.3 87.65 90 bottom
PC1144  22U_0603_6.3V6M  [C_0603]  85.1 87.65 90 bottom
PC1145  22U_0603_6.3V6M  [C_0603]  83.89 87.65 90 bottom
PC1146  22U_0603_6.3V6M  [C_0603]  122.4 61.15 180 top
PC1147  1U_0201_6.3V6M  [C_0201]  123.31 62.9 0 top
PC1148  1U_0201_6.3V6M  [C_0201]  122.15 66.48 90 top
PC1149  1U_0201_6.3V6M  [C_0201]  123.32 62.3 0 top
PC1150  1U_0201_6.3V6M  [C_0201]  123.52 59.87 0 top
PC1151  1U_0201_6.3V6M  [C_0201]  123.52 59.31 0 top
PC1152  1U_0201_6.3V6M  [C_0201]  121.37 66.57 180 top
PC1153  1U_0201_6.3V6M  [C_0201]  123.52 60.44 0 top
PC1175  22U_0603_6.3V6M  [C_0603]  84.27 62.95 90 bottom
PC1176  22U_0603_6.3V6M  [C_0603]  87.38 62.95 90 top
PC1177  22U_0603_6.3V6M  [C_0603]  87.38 62.95 90 bottom
PC1178  22U_0603_6.3V6M  [C_0603]  84.52 57.93 270 top
PC1179  22U_0603_6.3V6M  [C_0603]  85.54 62.95 90 top
PC1180  22U_0603_6.3V6M  [C_0603]  83.25 57.93 270 bottom
PC1181  22U_0603_6.3V6M  [C_0603]  84.52 57.93 270 bottom
PC1201  0.01UF 25V +-10% X7R 0402  [C_0402]  64.85 107.44 0 bottom
PC1202  0.47U 25V K X7R 0603  [C_0603]  8.84 52.03 270 top
PC1203  1500P_0402_50V7K  [C_0402]  9.38 42.61 0 top
PC1204  0.1U_0402_10V7K  [C_0402]  16.93 55.84 180 top
PC1205  100P_0402_50V8J~D  [C_0402]  67.33 111.28 0 bottom
PC1206  220P_0402_50V8J~D  [C_0402]  68.06 110.4 0 top
PC1207  1200P_0402_50V7K  [C_0402]  65.43 110.54 180 bottom
PC1208  1000P_0402_50V7K  [C_0402]  14.45 85.06 270 top
PC1209  0.1U_0402_25V6  [C_0402]  17.66 85.11 270 top
PC1210  1500P_0402_50V7K  [C_0402]  14.86 50.56 180 top
PC1211  100P_0402_50V8J  [C_0402]  68.46 106.8 90 top
PC1212  100P_0402_50V8J  [C_0402]  67.49 103.94 270 bottom
PC1213  1200P_0402_50V7K  [C_0402]  66.58 103.92 270 bottom
PC1214  0.01UF_0402_25V7K  [C_0402]  15.93 54.06 90 top
PC1215  100P_0402_50V8J  [C_0402]  15.31 89.22 90 bottom
PC1216  100P_0402_50V8J  [C_0402]  17.89 88.92 0 bottom
PC1217  1500P_0402_50V7K  [C_0402]  29.22 38.61 90 top
PC1321  330U_D2_2.5VM_R9M  [C_D2]  75.44 73.13 270 top
PC1322  22U_0603_6.3V6M  [C_0603]  109.99 58.69 180 top
PC1323  22U_0603_6.3V6M  [C_0603]  109.99 57.42 180 top
PC1324  22U_0603_6.3V6M  [C_0603]  109.99 56.22 180 top
PC1325  22U_0603_6.3V6M  [C_0603]  109.16 53.99 180 top
PC1326  22U_0603_6.3V6M  [C_0603]  109.99 61.17 180 top
PC1327  22U_0603_6.3V6M  [C_0603]  109.99 59.96 180 top
PC1328  1U_0201_6.3V6M  [C_0201]  103.73 68.09 0 top
PC1329  1U_0201_6.3V6M  [C_0201]  103.04 68.09 180 top
PC1330  1U_0201_6.3V6M  [C_0201]  110.11 64.94 90 top
PC1331  1U_0201_6.3V6M  [C_0201]  109.95 53.68 0 top
PC1332  1U_0201_6.3V6M  [C_0201]  109.95 54.25 0 top
PC1333  1U_0201_6.3V6M  [C_0201]  111.96 64.88 90 top
PC1334  1U_0201_6.3V6M  [C_0201]  109.23 64.94 90 top
PC1335  100P_0402_50V8J  [C_0402]  59.47 62.58 0 top
PD1  -  [TVNST52302AB0_SOT523-3]  18.99 2.78 180 top
PD2  -  [TVNST52302AB0_SOT523-3]  21.04 2.78 180 top
PD3  BAS40CW SOT-323  [DB3J315E0L_SMINI3-F2-B3]  59.44 77.17 180 top
PD4  -  [PESD5V0U2BT_SOT23-3]  63.38 86.36 180 bottom
PD5  S SCH DIO 5A 100V 15UA 0.88V TO227-3  [PDS5100H-13_POWERDI5-3]  44.64 84.22 90 top
PD6  -  [DFLS160-7_POWERDI123-2]  50.94 93.39 0 top
PD901  SDMK0340L-7-F_SOD323-2~D  [SDMK0340L-7-F_SOD323-2]  7.76 23.14 90 top
PD903  -  [RB520SM-30T2R_EMD2-2]  9.56 23.88 90 top
PD904  SDMK0340L-7-F_SOD323-2~D  [SDMK0340L-7-F_SOD323-2]  11.22 23.9 90 top
PD905  BAT54CW-7-F SOT-323  [BAT54CW_SOT323-3]  32.9 29.86 90 top
PD906  ZEN DIO SMF4L22A SOD123FL-2  [SMF22A-SOD123FL-2-S]  6.38 12.67 180 bottom
PD1202  S SCH DIO 5A 100V 15UA 0.88V TO227-3  [PDS5100H-13_POWERDI5-3]  6.48 44.98 90 top
PD1205  -  [SDMK0340L-7-F_SOD323-2]  70.52 107.02 270 bottom
PD1801  BAT54CW-7-F SOT-323  [BAT54CW_SOT323-3]  65.5 105.6 90 bottom
PH601  470K_0402_5%_B25/50 4700K  [R_0402]  62.21 74.62 0 bottom
PH602  10K_0402_5%_B25/50 4250K  [R_0402]  72.57 74.26 180 bottom
PH603  470K_0402_5%_B25/50 4700K  [R_0402]  54.31 57.17 0 bottom
PH604  10KB_0402_5%  [R_0402]  82.31 83.01 180 bottom
PH605  10K_0402_5%_B25/50 4250K  [R_0402]  66.48 58.25 0 bottom
PJP1  PAD-OPEN1X1M  [JUMP_43X39]  123.37 82.76 0 bottom
PJP2  PAD-OPEN1X1M  [JUMP_43X39]  144.28 88.55 270 bottom
PJP3  PAD-OPEN1X3M  [JUMP_43X118]  139.58 88.3 90 bottom
PJP4  PAD-OPEN1X1M  [JUMP_43X39]  156.72 54.76 0 top
PJP7  PAD-OPEN1X1M  [JUMP_43X39]  31.95 88.42 270 top
PJP8  PAD-OPEN 1X3M  [JUMP_43X118]  39.31 95.81 270 top
PJP12  PAD-OPEN1X1M  [JUMP_43X39]  100.21 84.99 270 bottom
PJP14  PAD-OPEN1X2M  [JUMP_43X79]  18 43.71 0 top
PJP15  PAD-OPEN1X1M  [JUMP_43X39]  277.63 70.17 90 top
PJP16  PAD-OPEN1X1M  [JUMP_43X39]  273.19 70.63 180 top
PJP17  PAD-OPEN1X2M  [JUMP_43X79]  271.93 67.46 0 top
PJP18  PAD-OPEN1X1M  [JUMP_43X39]  274.07 77.36 90 top
PJP19  PAD-OPEN1X1M  [JUMP_43X39]  305.88 42.42 90 top
PJP20  PAD-OPEN1X1M  [JUMP_43X39]  310.01 73.35 90 top
PJP21  PAD-OPEN1X1M  [JUMP_43X39]  312.3 73.35 90 top
PJP22  PAD-OPEN1X1M  [JUMP_43X39]  300.7 64.88 90 top
PJP31  PAD-OPEN1X3M  [JUMP_43X118]  262.43 21.25 0 bottom
PJP32  PAD-OPEN1X1M  [JUMP_43X39]  280.42 38.83 270 bottom
PJP33  PAD-OPEN1X1M  [JUMP_43X39]  278.14 37.91 90 bottom
PJP34  PAD-OPEN1X2M  [JUMP_43X79]  273.94 40.45 270 bottom
PJP35  PAD-OPEN1X1M  [JUMP_43X39]  217.43 17.34 90 top
PJP36  PAD-OPEN1X2M  [JUMP_43X79]  193.43 12.85 270 top
PJP37  PAD-OPEN1X1M  [JUMP_43X39]  278.26 53 0 bottom
PJP38  PAD-OPEN1X1M  [JUMP_43X39]  205.49 9.42 0 top
PJP39  PAD-OPEN1X3M  [JUMP_43X118]  202.57 4.34 270 top
PJP40  PAD-OPEN1X2M  [JUMP_43X79]  194.95 19.53 90 top
PJP41  PAD-OPEN1X3M  [JUMP_43X118]  279.44 46.25 0 bottom
PJP42  PAD-OPEN1X1M  [JUMP_43X39]  271.71 47.64 0 top
PJP100  PAD-OPEN 1X2M~D  [JUMP_43X79]  160.16 114.12 180 top
PJP101  PAD-OPEN 1X2M~D  [JUMP_43X79]  160.59 116.44 0 bottom
PJP102  -  [JUMP_43X118]  148.95 102.06 180 bottom
PJP103  -  [JUMP_43X118]  166.88 101.02 270 bottom
PJP200  -  [JUMP_43X118]  48.37 39.39 270 top
PJP201  -  [JUMP_43X39]  48.08 52.06 0 top
PJP202  PAD-OPEN 1X2M~D  [JUMP_43X79]  40.39 45.1 0 top
PJP301  PAD-OPEN 1X2M~D  [JUMP_43X79]  176.79 98.68 270 bottom
PJP302  -  [JUMP_43X118]  178.29 81.3 180 bottom
PJP391  PAD-OPEN1X1M  [JUMP_43X39]  176.71 35.39 0 top
PJP401  -  [JUMP_43X79]  143.39 103.04 270 top
PJP402  -  [JUMP_43X79]  133.92 103.61 270 top
PJP403  PAD-OPEN1X1M  [JUMP_43X39]  136.17 114.12 0 top
PJP404  PAD-OPEN1X1M  [JUMP_43X39]  134.73 115.81 180 top
PJP501  PAD-OPEN1X1M  [JUMP_43X39]  124.97 111.03 270 top
PJP502  PAD-OPEN1X1M  [JUMP_43X39]  120.43 101.97 270 top
PJP505  PAD-OPEN1X1M  [JUMP_43X39]  198.86 6.21 180 top
PJP506  PAD-OPEN1X1M  [JUMP_43X39]  192.39 8.17 90 top
PJP601  PAD-OPEN 4X4M  [JUMP_43X118]  45.6 61.97 270 bottom
PJP602  PAD-OPEN 1X2M~D  [JUMP_43X79]  55.34 65.73 180 bottom
PJP603  PAD-OPEN1X1M  [JUMP_43X39]  72.09 89.43 180 bottom
PJP901  PAD-OPEN 4X4M  [JUMP_43X118-NPM]  9.25 16.94 90 bottom
PJP1202  -  [JUMP_43X118]  8.89 54.93 270 top
PJPDC1  CVILU_CI0805M1HRC-NH  [CVILU_CI0805M1HRC-NH_5P-T]  58.55 90.6 180 bottom
PL1  FBMJ4516HS720NT_2P  [TAIYO_FBMJ4516HS720NT_2P]  26.52 6.59 270 top
PL2  FBMJ4516HS720NT_2P  [TAIYO_FBMJ4516HS720NT_2P]  24.2 6.58 270 top
PL3  BLM15AG102SN1D_2P  [MURAT_BLM15AG102SN1D_2P]  59.59 90.68 0 top
PL4  FBMJ4516HS720NT_2P  [TAIYO_FBMJ4516HS720NT_2P]  55.97 90.97 180 top
PL100  1.5UH_9A_20%_7X7X3_M  [L_7X7X3_M_2P]  157.49 106.13 270 bottom
PL101  1.5UH_9A_20%_7X7X3_M  [L_7X7X3_M_2P]  166.9 110.29 270 bottom
PL201  S COIL 1UH +-20% PCMB063T-1R0MS 12A  [CYNTE_PCMB063T-1R0MS_2P]  52.84 49.5 270 bottom
PL301  0.68UH_7.9A_20%_5X5X3_M  [L_5X5X3_M_2P]  180.85 90.14 270 bottom
PL402  1UH_1277AS-H-1R0N-P2_3.3A_30%  [MAG_MLV-FY12N1R0M-O1L_2P]  139.42 105.76 0 top
PL404  1UH_1277AS-H-1R0N-P2_3.3A_30%  [MAG_MLV-FY12N1R0M-O1L_2P]  128.91 108.22 0 top
PL405  3A_Z120_40M_0603_2P  [3A_Z120_0603_2P]  137.19 117.53 270 top
PL406  3A_Z120_40M_0603_2P  [3A_Z120_0603_2P]  135.55 117.61 180 top
PL501  1UH_1277AS-H-1R0N-P2_3.3A_30%  [MAG_MLV-FY12N1R0M-O1L_2P]  123.16 104.31 270 top
PL502  3A_Z120_40M_0603_2P  [3A_Z120_0603_2P]  123.07 112.01 270 top
PL602  9A Z80 10M 1812_2P  [9A_Z80_1812_2P-NPM]  45.6 63.26 270 bottom
PL610  0.15UH_MMD-06CZER15MEX5L__35A_20%  [L_7X7X3_M]  71 70.12 180 bottom
PL612  0.15UH_MMD-06CZER15MEX5L__35A_20%  [L_7X7X3_M]  70.85 62.5 180 bottom
PL613  0.15UH_MMD-06CZER15MEX5L__35A_20%  [L_7X7X3_M]  78.23 78.95 180 bottom
PL614  0.47UH_MMD05CZR47M_12A_20%  [MAG_MMD05CZR47M_4P]  81.36 86.31 180 bottom
PL901  1UH +-20% 6.6A 5X5X3 MOLDING  [MAGLA_MMD-05CZ-1R0M-M7L_2P]  9.24 19.55 270 bottom
PL902  2.2UH_PCMB103T-2R2MS_13A_20%  [CYNTE_PCMB103T-2R2MS_2P]  18.27 25.16 0 bottom
PL1201  FBMA-L11-201209-800LMA50T  [TAI-T_HCB2012KF-121T50_2P]  15.57 85.78 0 bottom
PL1202  FBMA-L11-201209-800LMA50T  [TAI-T_HCB2012KF-121T50_2P]  15.57 87.5 0 bottom
PQ1  -  [DMN65D8LDW-7_SOT363-6]  60.19 106.12 90 top
PQ2  -  [FDV301N-G_SOT23-3]  63.51 91.12 180 top
PQ3  MMST3904-7-F_SOT323~D  [MMST3904-7-F_SOT323-3]  60.82 89 90 top
PQ4  EMZB08P03V 1P EDFN3X3-8  [FDMC6679AZ_MLP8-5]  47.88 84.6 270 top
PQ5  AO3409 P-CHANNEL SOT-23  [NTR4502PT1G_SOT23-3]  60.69 103.27 90 top
PQ6  L2N7002WT1G_SC70-3  [DMN65D8LW-7_SOT323-3]  57.11 92.8 90 top
PQ7  L2N7002WT1G_SC70-3  [DMN65D8LW-7_SOT323-3]  64.58 103.07 270 top
PQ8  L2N7002WT1G_SC70-3  [DMN65D8LW-7_SOT323-3]  62.23 102.85 270 bottom
PQ9  EMZB08P03VL 1P EDFN3X3-8  [FDMC6679AZ_MLP8-5]  49.92 89.55 180 top
PQ614  PE642DT 2N PDFN3X3S  [AON7934_DFN3X3A8-10]  72.49 87.66 0 bottom
PQ904  AOE6936 2N DFN5X6E  [AOE6930_DFN5X6E8-10]  32.62 15.71 180 bottom
PQ905  AOE6936 2N DFN5X6E  [AOE6930_DFN5X6E8-10]  9.42 24.91 90 bottom
PQ906  EMZB08P03V 1P EDFN3X3-8  [FDMC6679AZ_MLP8-5]  30.49 5.02 180 top
PQ909  L2N7002WT1G 1N SC-70-3  [DMN65D8LW-7_SOT323-3]  34.74 32.72 90 top
PQ1201  -  [DMN65D8LDW-7_SOT363-6]  14.95 34.68 0 top
PQ1202  EMZB08P03V 1P EDFN3X3-8  [FDMC6679AZ_MLP8-5]  10.11 46.11 270 top
PQ1203  AO3409 P-CHANNEL SOT-23  [NTR4502PT1G_SOT23-3]  8.07 40.22 90 top
PQ1204  -  [DMN65D8LDW-7_SOT363-6]  13.35 33.46 270 top
PQ1205  L2N7002WT1G_SC70-3  [DMN65D8LW-7_SOT323-3]  20.22 32.67 90 top
PQ1206  EMZB08P03V 1P EDFN3X3-8  [FDMC6679AZ_MLP8-5]  12.58 52.47 0 top
PQ1207  S TR DMN65D8LDW-7 2N SOT363-6  [DMN66D0LDW-7_SOT363-6]  34.93 38.44 180 top
PQ1208  S TR DMN65D8LDW-7 2N SOT363-6  [DMN66D0LDW-7_SOT363-6]  27.61 30.82 0 top
PQ1209  -  [DMN65D8LDW-7_SOT363-6]  18.79 53.42 90 top
PQ1210  S TR DMN65D8LDW-7 2N SOT363-6  [DMN66D0LDW-7_SOT363-6]  28.15 40.53 180 top
PQ1211  S TR DMN65D8LDW-7 2N SOT363-6  [DMN66D0LDW-7_SOT363-6]  31.9 38.81 180 top
PQ1212  L2N7002WT1G_SC70-3  [DMN65D8LW-7_SOT323-3]  70.21 107.17 180 top
PQ1213  EMZB08P03V 1P EDFN3X3-8  [FDMC6679AZ_MLP8-5]  12.41 50.47 180 top
PQ1214  -  [DMN65D8LDW-7_SOT363-6]  11.29 34.63 0 top
PQ1215  AO3409 P-CHANNEL SOT-23  [NTR4502PT1G_SOT23-3]  3.62 51.17 0 top
PQ1216  L2N7002WT1G_SC70-3  [DMN65D8LW-7_SOT323-3]  9.17 14.84 0 top
PR1  100K_0402_5%  [R_0402]  17.48 3.31 90 top
PR2  1K_0402_5%  [R_0402]  62.1 79.3 180 top
PR3  0_0402_5%  [R_0402]  63.03 92.83 0 top
PR4  2.2K_0402_5%  [R_0402]  64.94 93.74 180 top
PR5  33_0402_5%  [R_0402]  64.94 91.86 90 top
PR6  100K_0402_1%  [R_0402]  57.81 90.67 0 top
PR7  10K_0402_1%  [R_0402]  62.03 92.78 270 top
PR8  15K_0402_1%  [R_0402]  57.82 88.89 90 top
PR10  300K_0402_5%  [R_0402]  56.52 102.96 90 top
PR11  499K_0402_1%  [R_0402]  46.76 79.77 0 top
PR12  1M_0402_5%  [R_0402]  49.93 91.84 180 top
PR13  4.7K_0805_5%  [R_0805]  52.26 89.24 270 top
PR14  100K_0402_5%  [R_0402]  52.08 84.73 0 top
PR15  100K_0402_5%  [R_0402]  56.52 104.73 90 top
PR16  49.9K_0402_1%  [R_0402]  61.55 101.31 0 top
PR17  100K_0402_5%  [R_0402]  63.07 107.59 180 top
PR18  1M_0402_5%  [R_0402]  54.97 93.26 0 top
PR19  0_0402_5%  [R0402_0OHM]  61.22 106.65 90 top
PR20  0_0402_5%  [R0402_0OHM]  63.56 104.79 90 top
PR21  0_0402_5%  [R0402_0OHM]  62.22 94.35 90 bottom
PR22  0_0402_5%  [R0402_0OHM]  66.43 96.16 270 bottom
PR23  0_0402_5%  [R0402_0OHM]  61.02 93.54 180 top
PR24  100K_0402_5%  [R_0402]  63.1 106.65 180 top
PR25  0_0402_5%  [R0402_0OHM]  57.08 106.95 180 top
PR26  0_0402_5%  [R0402_0OHM]  67.65 99.78 180 bottom
PR27  100K_0402_5%  [R_0402]  66.73 98.76 0 bottom
PR28  100K_0402_5%  [R_0402]  61.79 103.91 90 bottom
PR29  0_0402_5%  [R0402_0OHM]  65.26 102.19 90 bottom
PR30  100K_0402_5%  [R_0402]  60.1 94.35 0 top
PR100  0_0603_5%  [R0603_0OHM]  158.37 111.46 0 top
PR102  499K_0402_1%  [R_0402]  171.63 117.94 0 bottom
PR103  499K_0402_1%  [R_0402]  171.63 118.83 0 bottom
PR104  0_0402_5%  [R0402_0OHM]  152.55 111.09 180 top
PR105  0_0402_5%  [R0402_0OHM]  152.55 110.2 180 top
PR106  4.7_1206_5%  [R_1206]  156.28 109.05 0 bottom
PR107  100K_0402_5%  [R_0402]  153.04 116.05 270 top
PR108  1K_0402_5%  [R_0402]  150.62 112.65 270 top
PR111  0_0603_5%  [R0603_0OHM]  164.8 113.27 180 bottom
PR112  4.7_1206_5%  [R_1206]  162.17 110.66 270 bottom
PR113  100K_0402_5%  [R_0402]  170.07 118.42 270 bottom
PR114  0_0402_5%  [R0402_0OHM]  173.36 116.5 270 bottom
PR116  1M_0402_1%  [R_0402]  172.47 115.59 90 bottom
PR117  1K_0402_5%  [R_0402]  172.97 114.64 0 bottom
PR119  0_0402_5%  [R0402_0OHM]  153.93 115.13 90 top
PR120  0_0402_5%  [R0402_0OHM]  169.19 117.51 90 bottom
PR202  4.7_1206_5%  [R_1206]  51.98 49.13 180 top
PR203  0_0603_5%  [R0603_0OHM]  47.9 47.42 0 top
PR204  102K_0402_1%  [R_0402]  46.17 44.65 90 bottom
PR205  0_0402_5%  [R_0402]  42.61 45.56 270 bottom
PR206  100K_0402_1%  [R_0402]  44.39 45.56 270 bottom
PR207  0_0402_5%  [R_0402]  43.5 44.65 90 bottom
PR208  0_0402_5%  [R0402_0OHM]  40.26 52.1 270 bottom
PR209  1M_0402_5%  [R_0402]  41.15 51.19 90 bottom
PR210  0_0402_5%  [R0402_0OHM]  42.98 52.06 270 bottom
PR212  1M_0402_5%  [R_0402]  44.72 51.14 90 bottom
PR302  1M_0402_1%  [R_0402]  184.14 98.57 0 bottom
PR303  4.7_1206_5%  [R_1206]  177.23 90.32 180 bottom
PR304  0_0603_5%  [R0603_0OHM]  176.47 91.97 0 bottom
PR306  21.5K_0402_1%  [R_0402]  185.06 93.11 180 bottom
PR307  0_0402_5%  [R_0402]  185.06 96.73 180 bottom
PR308  1K_0402_5%  [R_0402]  185.06 94 180 bottom
PR310  0_0402_5%  [R_0402]  184.14 95.84 0 bottom
PR311  31.6K_0402_1%  [R_0402]  184.14 94.89 0 bottom
PR312  0_0402_5%  [R0402_0OHM]  185.06 97.68 180 bottom
PR402  0_0402_5%  [R0402_0OHM]  136.56 110.51 0 top
PR403  1M_0402_1%  [R_0402]  137.46 112.3 180 top
PR404  0_0402_5%  [R_0402]  137.4 108.68 0 top
PR405  4.7_0603_5%  [R_0603]  138.14 105.33 90 top
PR406  0_0402_5%  [R0402_0OHM]  127.04 112.87 0 top
PR407  1M_0402_1%  [R_0402]  127.05 113.75 90 top
PR408  0_0402_5%  [R_0402]  125.39 113.22 90 top
PR409  4.7_0603_5%  [R_0603]  127.26 107.71 90 top
PR410  0_0402_5%  [R_0402]  127.03 111.05 0 top
PR411  0_0402_5%  [R_0402]  122.77 113.22 90 top
PR412  0_0402_5%  [R_0402]  144.71 109.52 0 top
PR413  10K_0402_1%  [R_0402]  145.19 112.31 180 top
PR414  10K_0402_1%  [R_0402]  145.19 113.2 180 top
PR415  10K_0402_1%  [R_0402]  143.41 112.57 90 top
PR416  10K_0402_1%  [R_0402]  143.49 114.52 180 top
PR417  10K_0402_1%  [R_0402]  123.63 113.22 90 top
PR418  10K_0402_1%  [R_0402]  124.51 113.22 90 top
PR419  10K_0402_1%  [R_0402]  123.67 114.99 180 top
PR420  10K_0402_1%  [R_0402]  124.49 115 0 top
PR421  0_0402_5%  [R_0402]  145.62 107.74 180 top
PR422  0_0402_5%  [R_0402]  144.71 108.63 0 top
PR423  0_0402_5%  [R0402_0OHM]  133.76 110.44 0 top
PR424  100K_0402_1%  [R_0402]  133.76 111.31 0 top
PR425  0_0402_5%  [R0402_0OHM]  137.4 109.6 0 top
PR426  0_0402_5%  [R0402_0OHM]  127.03 111.96 0 top
PR427  0_0402_5%  [R_0402]  144.71 110.53 0 top
PR428  1M_0402_1%  [R_0402]  133.77 113.07 0 top
PR501  20K_0402_1%  [R_0402]  120.07 108.79 0 top
PR502  4.7_0603_5%  [R_0603]  125.76 104.08 90 top
PR504  0_0402_5%  [R0402_0OHM]  119.69 107.64 0 top
PR505  1M_0402_1%  [R_0402]  120.61 106.73 180 top
PR506  10K_0402_1%  [R_0402]  121.04 110.56 90 top
PR513  0_0402_5%  [R0402_0OHM]  198.5 3.98 180 top
PR514  1M_0402_1%  [R_0402]  198.48 3.11 270 top
PR515  21.5K_0402_1%  [R_0402]  190.99 3.29 0 top
PR516  10.2K_0402_1%  [R_0402]  191.91 2.42 180 top
PR517  100K_0402_5%  [R_0402]  121.99 110.56 90 top
PR601  45.3_0402_1%  [R_0402]  73.76 50.78 0 bottom
PR602  0_0402_5%  [R0402_0OHM]  74.31 46.89 0 top
